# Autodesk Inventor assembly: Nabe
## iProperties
Author: 42964
Shininess: 20.0
PropertySet Name: _Private Model Information
Length Units: 11269
Angle Units: 11283
Time Units: 11279
Mass Units: 11290
Length Display Precision: 3
Angle Display Precision: 2
Compacted: False
Created: 2001-02
Part Number: Nabe
Document SubType Name: Assembly
Designer: 42964
Control State: 0
Master: False
Checked Out: False
PropertySet Name: Design Tracking Control
Density: 0.0
Volumn: 0.0
Area: 0.0
PropertySet Name: Model Information
